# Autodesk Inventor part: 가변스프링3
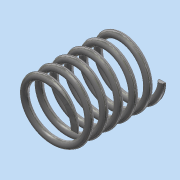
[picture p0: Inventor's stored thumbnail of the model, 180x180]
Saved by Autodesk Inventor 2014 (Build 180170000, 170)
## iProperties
Created: 2023-01
Part Number: 가변스프링3
Material: 스테인레스 스틸
Document SubType Name: Modeling
Designer: dg
Density: 8.08 g/cm^3
Appearance: 반연마
Mass: 7.99982 g
Surface Area: 20.0872 cm^2
Volume: 0.990077 cm^3
Author: dg
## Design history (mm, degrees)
sketch "스케치1"
  geometry: L1 (8.5, 0)-(0, 0); L2 (0, 0)-(0, 26.33); L3 (0, 26.33)-(8.5, 26.33); C1 r 1 at (8.5, 0)
  constraints: 6 end point, 1 centre point, 1 coincident, 1 horizontal, 1 parallel, 1 vertical, 1 vertical alignment
  dimensions: "d0" = 2 diameter of C1; "d1" = 26.33013 distance of L1.end L2.end (derived); "d2" = 17 diameter of L1.start L2
feature "코일1" sketch "스케치1" pitch "d3" = 10; turns "d5" = 6; dims "d4" = 26.33013 (= d1), "d6" = 0, angle "d7" = 90 deg, angle "d8" = 90 deg, "d9" = 0, "d10" = 0
node "작업 평면1"
node "작업 평면2"
feature "분할1"
feature "분할2"
node "솔리드1"
other parameters: "d11" = 90 deg, "d12" = 90 deg
